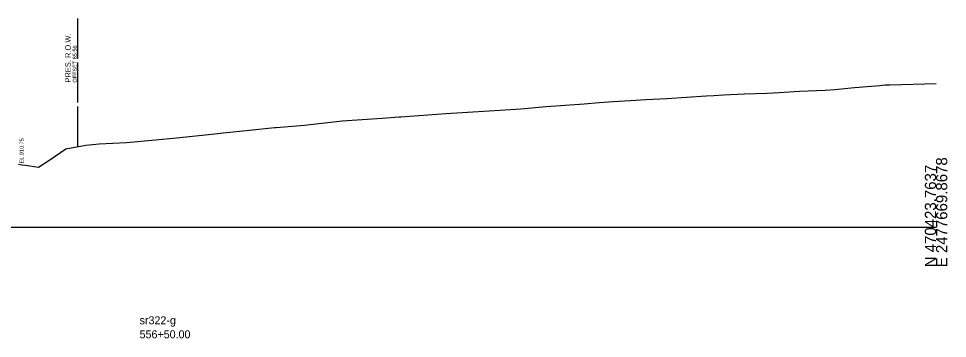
# Model space of a CAD drawing. Extents: x -26 to 4781, y -31 to 24738.
# Drawn here: x 2370.8 to 2602.8, y 6972.2 to 7052.1 of the extents above; entities that cross this region are included whole.
import ezdxf

# ---------------------------------------------------------------- set-up
doc = ezdxf.new("R2010")
doc.units = 0
for name, color, linetype in [('DESIGN - SHEET - Light Grid', 7, 'Continuous'), ('DESIGN - TYPICAL - Warning Text', 7, 'Continuous'), ('SURVEY - GROUND - Existing Pavement Text', 7, 'Continuous'), ('SURVEY - GROUND - Top of Ground', 7, 'Continuous'), ('SURVEY - PROPERTY - ROW Lines', 7, 'Continuous'), ('SURVEY - PROPERTY - ROW Lines Text', 7, 'Continuous')]:
    doc.layers.add(name, color=color, linetype=linetype)

msp = doc.modelspace()

# ---------------------------------------------------------------- linework, layer by layer
at = {"layer": 'DESIGN - SHEET - Light Grid'}
msp.add_line((2300, 7000), (2600, 7000), dxfattribs=at)
at = {"layer": 'SURVEY - GROUND - Top of Ground'}
msp.add_lwpolyline([(2370.75, 7015.72), (2371.06, 7015.71), (2372.39, 7015.48), (2373.58, 7015.31), (2375.73, 7015.01), (2378.36, 7016.7), (2382.59, 7019.6), (2387.56, 7020.5), (2390.89, 7020.84), (2397.72, 7021.2), (2404.96, 7021.8), (2410.25, 7022.31), (2419.79, 7023.38), (2421.88, 7023.6), (2428.42, 7024.25), (2434.72, 7024.89), (2435.13, 7024.93), (2442.18, 7025.52), (2451.59, 7026.55), (2461.64, 7027.27), (2465.88, 7027.58), (2466.28, 7027.61), (2477.52, 7028.4), (2481.63, 7028.69), (2489.64, 7029.18), (2496.27, 7029.59), (2502.55, 7030.13), (2512.07, 7030.87), (2515.82, 7031.13), (2519.34, 7031.39), (2523.55, 7031.66), (2527.46, 7031.89), (2532.71, 7032.21), (2542.6, 7032.82), (2544.51, 7032.94), (2546.92, 7033.1), (2552.16, 7033.33), (2557.8, 7033.54), (2560.82, 7033.67), (2565.88, 7033.97), (2572.28, 7034.26), (2574.68, 7034.45), (2579.61, 7034.89), (2585.97, 7035.44), (2587.28, 7035.55), (2588.44, 7035.6), (2600, 7035.95)], dxfattribs=at)
at = {"layer": 'SURVEY - PROPERTY - ROW Lines'}
for p, q in [((2385.56, 7042.14), (2385.56, 7052.14)), ((2385.56, 7031.14), (2385.56, 7041.14)), ((2385.56, 7020.14), (2385.56, 7030.14))]:
    msp.add_line(p, q, dxfattribs=at)

# ---------------------------------------------------------------- texts
at = {"layer": 'DESIGN - SHEET - Light Grid'}
for s, p in [('E 2477669.8678', (2602.8, 6990)), ('N 470423.7637', (2600, 6990))]:
    msp.add_text(s, height=2.8, rotation=90, dxfattribs=at).set_placement(p)
at = {"layer": 'DESIGN - TYPICAL - Warning Text'}
for s, p in [('sr322-g', (2401, 6975.75)), ('556+50.00', (2401, 6972.25))]:
    msp.add_text(s, height=2, dxfattribs=at).set_placement(p)
at = {"layer": 'SURVEY - GROUND - Existing Pavement Text'}
msp.add_text('EL.910.75', height=1, rotation=90, dxfattribs=at).set_placement((2372.03, 7015.95))
at = {"layer": 'SURVEY - PROPERTY - ROW Lines Text'}
for s, height, p in [('PRES. R.O.W.', 1.4, (2383.81, 7036.14)), ('OFFSET 85.56', 1, (2385.31, 7036.14))]:
    msp.add_text(s, height=height, rotation=90, dxfattribs=at).set_placement(p)

doc.saveas('drawing.dxf')
